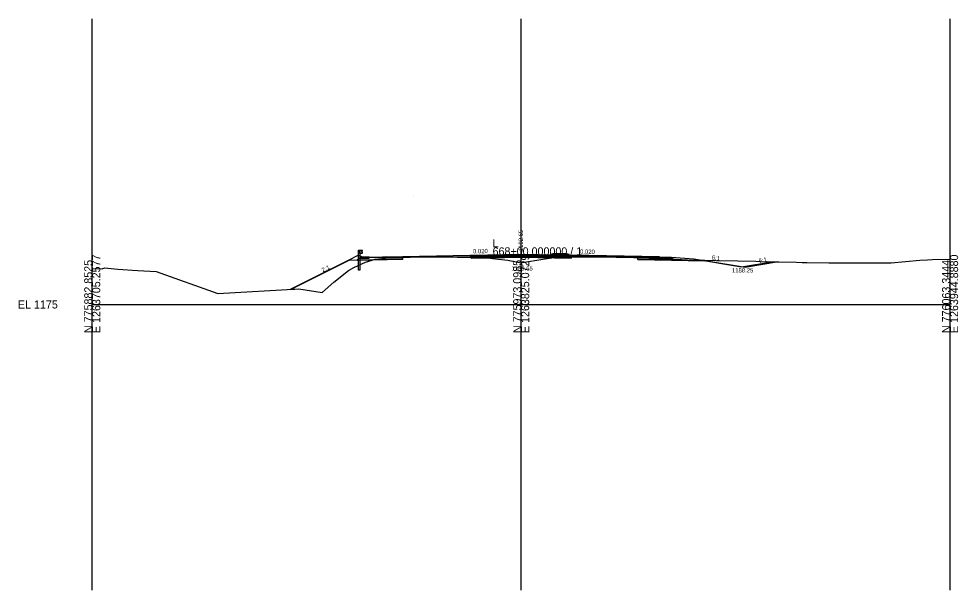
# Model space of a CAD drawing. Extents: x -41 to 1262860, y -100 to 777489.
# Drawn here: x -25.7 to 302.8, y 2435 to 2635 of the extents above; entities that cross this region are included whole.
import ezdxf

# ---------------------------------------------------------------- set-up
doc = ezdxf.new("R2010")
doc.units = 0
for name, color, linetype in [('Exist Cross Section Cell', 7, 'Continuous'), ('Exist XS Center Line Elevation Label', 7, 'Continuous'), ('Exist XS Ground Line', 7, 'Continuous'), ('Prop CMT Guardrail Graphics', 7, 'Continuous'), ('Prop CMT Pvmt Course 1', 7, 'Continuous'), ('Prop CMT Pvmt Course 4', 7, 'Continuous'), ('Prop CMT Pvmt Surface', 7, 'Continuous'), ('Prop CMT Shld Paved Course 1', 7, 'Continuous'), ('Prop CMT Shld Paved Course 2', 7, 'Continuous'), ('Prop CMT Shld Paved Course 4', 7, 'Continuous'), ('Prop CMT Slope Grass', 7, 'Continuous'), ('Prop CMT Subgrade Earthwork', 7, 'Continuous'), ('Prop Conc Curb and Gutter', 7, 'Continuous'), ('Prop Conc Island Cover', 7, 'Continuous'), ('Prop XS Ditch Standard Text', 7, 'Continuous'), ('Prop XS Earthwork Shape', 7, 'Continuous'), ('Prop XS Exc Vertical Line 1', 7, 'Continuous'), ('Prop XS Exc Vertical Line 2', 7, 'Continuous'), ('Prop XS Exc Vertical Line 3', 7, 'Continuous'), ('Prop XS Finish Grade', 7, 'Continuous'), ('Prop XS Hydro Elevations', 7, 'Continuous'), ('Prop XS SE Text', 7, 'Continuous'), ('Prop XS Side Slope Text', 7, 'Continuous'), ('Scratch_Level_4', 7, 'Continuous'), ('Scratch_Level_6', 7, 'Continuous'), ('Typical Curb CELL', 7, 'Continuous')]:
    doc.layers.add(name, color=color, linetype=linetype)

msp = doc.modelspace()

# ---------------------------------------------------------------- linework, layer by layer
at = {"layer": 'Exist Cross Section Cell'}
for p, q in [((150, 2535), (150, 2555)), ((0, 2535), (150, 2535)), ((150, 2535), (300, 2535))]:
    msp.add_line(p, q, dxfattribs=at)
at = {"layer": 'Exist XS Ground Line'}
msp.add_lwpolyline([(0, 2547.6), (3.47, 2547.54), (4.24, 2547.78), (8.95, 2547.37), (10.74, 2547.26), (14.03, 2547.01), (15.91, 2546.85), (22.35, 2546.58), (43.91, 2538.86), (72.29, 2540.43), (80.41, 2539.24), (84.48, 2542.76), (89.57, 2546.93), (91.48, 2547.93), (95.5, 2549.87), (98.14, 2550.65), (98.83, 2550.86), (102.58, 2551.18), (106.45, 2551.46), (108.07, 2551.54), (111.16, 2551.67), (120, 2551.72), (123.66, 2551.73), (134.58, 2551.43), (135.86, 2551.39), (135.97, 2551.39), (139.17, 2551.26), (139.43, 2551.23), (139.92, 2551.15), (145.28, 2550.51), (147.7, 2550.07), (150.05, 2549.64), (150.46, 2549.72), (157.54, 2550.92), (161.28, 2551.47), (162.98, 2551.54), (164.83, 2551.61), (170.78, 2551.65), (177.02, 2551.72), (189.41, 2551.47), (189.73, 2551.46), (189.77, 2551.46), (190.84, 2551.41), (196.52, 2551.13), (197.22, 2551.09), (200.74, 2550.94), (201.72, 2550.94), (208.2, 2550.67), (214.27, 2550.52), (218.16, 2550.35), (225.75, 2550.24), (232.05, 2550.15), (233.67, 2550.1), (238.66, 2549.93), (246.24, 2549.78), (248.32, 2549.74), (249.85, 2549.73), (257.58, 2549.6), (263.86, 2549.57), (269.63, 2549.57), (276.92, 2549.58), (278.52, 2549.57), (279.35, 2549.6), (289.37, 2550.47), (292.11, 2550.68), (293.83, 2550.76), (300, 2550.85)], dxfattribs=at)
at = {"layer": 'Prop CMT Guardrail Graphics'}
for p, q in [((93.11, 2554.05), (93.59, 2554.05)), ((93.11, 2551.55), (93.11, 2554.05)), ((93.59, 2552.87), (93.59, 2554.05)), ((93.59, 2554.05), (94.26, 2554.05)), ((93.59, 2554.05), (93.59, 2551.54)), ((94.26, 2552.87), (93.59, 2552.87)), ((94.26, 2554.05), (94.26, 2552.87)), ((94.26, 2553.97), (94.26, 2552.95)), ((94.36, 2553.95), (94.26, 2553.97)), ((94.26, 2552.95), (94.36, 2552.97)), ((94.27, 2553.5), (94.5, 2553.71)), ((94.27, 2553.41), (94.27, 2553.5)), ((94.5, 2553.21), (94.27, 2553.41)), ((94.5, 2553.85), (94.36, 2553.95)), ((94.36, 2552.97), (94.5, 2553.07)), ((94.5, 2553.71), (94.5, 2553.85)), ((94.5, 2553.07), (94.5, 2553.21)), ((93.11, 2547.05), (93.11, 2551.55)), ((93.59, 2551.54), (93.59, 2547.05)), ((93.59, 2547.05), (93.11, 2547.05))]:
    msp.add_line(p, q, dxfattribs=at)
at = {"layer": 'Prop CMT Pvmt Course 1'}
for p, q in [((132.5, 2552.05), (150, 2552.4)), ((150, 2552.4), (167.5, 2552.05))]:
    msp.add_line(p, q, dxfattribs=at)
for points in [[(108.5, 2551.57), (108.5, 2551.82), (108.5, 2551.82), (132.16, 2552.29), (132.16, 2552.29), (132.43, 2552.3), (132.43, 2552.3), (132.5, 2552.3), (132.5, 2552.05), (132.5, 2552.05), (132.43, 2552.05), (132.43, 2552.05), (132.16, 2552.04), (132.16, 2552.04), (108.5, 2551.57), (108.5, 2551.57), (108.5, 2551.57)], [(198.36, 2551.43), (198.36, 2551.68), (198.36, 2551.68), (167.5, 2552.3), (167.5, 2552.3), (167.5, 2552.05), (167.5, 2552.05), (167.5, 2552.05), (198.36, 2551.43), (198.36, 2551.43), (198.36, 2551.43)]]:
    msp.add_lwpolyline(points, dxfattribs=at)
at = {"layer": 'Prop CMT Pvmt Course 4'}
for p, q in [((108.5, 2550.78), (93.44, 2550.48)), ((132.5, 2551.72), (132.5, 2551.26)), ((132.5, 2551.26), (150, 2551.61)), ((150, 2551.61), (167.5, 2551.26)), ((190.84, 2550.79), (203.55, 2550.54)), ((198.36, 2550.64), (198.36, 2551.1)), ((203.08, 2551), (203.55, 2550.54))]:
    msp.add_line(p, q, dxfattribs=at)
at = {"layer": 'Prop CMT Pvmt Surface'}
for p, q in [((96.85, 2551.59), (108.5, 2551.82)), ((108.5, 2551.82), (132.5, 2552.3)), ((132.5, 2552.3), (150, 2552.65)), ((150, 2552.65), (167.5, 2552.3)), ((167.5, 2552.3), (198.36, 2551.68)), ((198.36, 2551.68), (202.48, 2551.6))]:
    msp.add_line(p, q, dxfattribs=at)
at = {"layer": 'Prop CMT Shld Paved Course 1'}
for p, q in [((94.5, 2551.54), (108.5, 2551.82)), ((108.5, 2551.57), (96.85, 2551.34)), ((104.5, 2551.74), (104.5, 2551.74)), ((108.5, 2551.82), (108.5, 2551.57)), ((108.5, 2551.57), (108.5, 2551.57)), ((132.5, 2552.3), (150, 2552.65)), ((150, 2552.65), (167.5, 2552.3))]:
    msp.add_line(p, q, dxfattribs=at)
msp.add_lwpolyline([(198.36, 2551.68), (202.48, 2551.6), (202.48, 2551.6), (202.74, 2551.34), (198.36, 2551.43), (198.36, 2551.43), (198.36, 2551.43), (198.36, 2551.68), (198.36, 2551.68)], dxfattribs=at)
at = {"layer": 'Prop CMT Shld Paved Course 2'}
for p, q in [((112.18, 2573.18), (112.18, 2573.18)), ((112.18, 2573.18), (112.18, 2573.18)), ((112.18, 2573.18), (112.18, 2573.18)), ((112.18, 2573.18), (112.18, 2573.18)), ((108.5, 2551.24), (101.64, 2551.1)), ((103.9, 2551.14), (103.9, 2551.14)), ((103.9, 2551.14), (103.9, 2551.14)), ((111.16, 2551.62), (108.5, 2551.57)), ((108.5, 2551.56), (109.05, 2551.58)), ((108.5, 2551.57), (108.5, 2551.24)), ((108.5, 2551.57), (108.5, 2551.57)), ((108.5, 2551.57), (108.5, 2551.56)), ((108.5, 2551.56), (108.5, 2551.56)), ((108.5, 2551.24), (108.5, 2551.24)), ((109.05, 2551.58), (111.16, 2551.62)), ((109.05, 2551.58), (109.05, 2551.58)), ((120, 2551.8), (111.16, 2551.62)), ((111.16, 2551.62), (114.6, 2551.69)), ((111.16, 2551.62), (111.16, 2551.62)), ((111.16, 2551.62), (111.16, 2551.62)), ((111.16, 2551.62), (111.16, 2551.62)), ((111.16, 2551.62), (111.16, 2551.62)), ((114.6, 2551.69), (120, 2551.72)), ((114.6, 2551.69), (114.6, 2551.69)), ((123.66, 2551.87), (120, 2551.8)), ((120, 2551.8), (120, 2551.8)), ((120, 2551.72), (123.66, 2551.73)), ((120, 2551.72), (120, 2551.72)), ((132.16, 2552.04), (123.66, 2551.87)), ((123.66, 2551.87), (123.66, 2551.87)), ((123.66, 2551.87), (123.66, 2551.87)), ((123.66, 2551.73), (123.66, 2551.73)), ((123.66, 2551.73), (127.63, 2551.62)), ((127.63, 2551.62), (132.16, 2551.71)), ((127.63, 2551.62), (127.63, 2551.62)), ((127.63, 2551.62), (127.63, 2551.62)), ((132.43, 2552.05), (132.16, 2552.04)), ((132.16, 2552.04), (132.16, 2552.04)), ((132.16, 2551.71), (132.16, 2551.71)), ((132.16, 2551.71), (132.43, 2551.71)), ((132.5, 2552.05), (132.43, 2552.05)), ((132.43, 2551.71), (132.5, 2551.72)), ((132.5, 2551.72), (150, 2552.07)), ((132.5, 2551.72), (132.5, 2552.05)), ((132.5, 2552.05), (132.5, 2552.05)), ((132.5, 2551.72), (132.5, 2551.72)), ((132.5, 2551.72), (132.5, 2551.72)), ((150, 2552.07), (167.5, 2551.72)), ((167.5, 2551.72), (167.5, 2552.05)), ((167.5, 2552.05), (170.78, 2551.98)), ((170.74, 2551.65), (167.5, 2551.72)), ((167.5, 2551.72), (167.5, 2551.72)), ((167.5, 2551.72), (167.5, 2551.72)), ((170.78, 2551.65), (170.74, 2551.65)), ((170.78, 2551.98), (170.78, 2551.98)), ((170.78, 2551.98), (177.02, 2551.86)), ((177.02, 2551.72), (170.78, 2551.65)), ((170.78, 2551.65), (170.78, 2551.65)), ((177.02, 2551.86), (177.02, 2551.86)), ((177.02, 2551.86), (177.02, 2551.86)), ((177.02, 2551.86), (189.41, 2551.61)), ((189.41, 2551.47), (177.02, 2551.72)), ((177.02, 2551.72), (177.02, 2551.72)), ((177.02, 2551.72), (177.02, 2551.72)), ((189.41, 2551.61), (189.41, 2551.61)), ((189.41, 2551.61), (189.73, 2551.61)), ((189.73, 2551.46), (189.41, 2551.47)), ((189.41, 2551.47), (189.41, 2551.47)), ((189.73, 2551.61), (189.77, 2551.6)), ((189.77, 2551.46), (189.73, 2551.46)), ((189.77, 2551.6), (189.77, 2551.6)), ((189.77, 2551.6), (190.84, 2551.58)), ((190.84, 2551.41), (189.77, 2551.46)), ((189.77, 2551.46), (189.77, 2551.46)), ((190.84, 2551.58), (190.84, 2551.58)), ((190.84, 2551.58), (190.84, 2551.58)), ((190.84, 2551.58), (190.84, 2551.58)), ((190.84, 2551.58), (190.84, 2551.58)), ((190.84, 2551.58), (196.52, 2551.47)), ((190.84, 2551.25), (190.84, 2551.41)), ((190.84, 2551.41), (190.84, 2551.41)), ((190.84, 2551.41), (190.84, 2551.41)), ((190.84, 2551.41), (190.84, 2551.41)), ((197.22, 2551.12), (190.84, 2551.25)), ((196.52, 2551.47), (197.22, 2551.46)), ((196.52, 2551.47), (196.52, 2551.47)), ((196.52, 2551.47), (196.52, 2551.47)), ((197.22, 2551.46), (197.22, 2551.46)), ((197.22, 2551.46), (198.36, 2551.43)), ((198.36, 2551.1), (197.22, 2551.12)), ((197.22, 2551.12), (197.22, 2551.12)), ((198.36, 2551.43), (198.36, 2551.1)), ((198.36, 2551.1), (198.36, 2551.1))]:
    msp.add_line(p, q, dxfattribs=at)
msp.add_lwpolyline([(198.36, 2551.43), (202.74, 2551.34), (202.74, 2551.34), (203.08, 2551), (198.36, 2551.1), (198.36, 2551.1), (198.36, 2551.1), (198.36, 2551.43), (198.36, 2551.43)], dxfattribs=at)
at = {"layer": 'Prop CMT Shld Paved Course 4'}
for p, q in [((112.18, 2573.18), (112.18, 2573.18)), ((112.18, 2573.18), (112.18, 2573.18)), ((92.58, 2550.46), (93.32, 2551.2)), ((93.32, 2551.2), (93.83, 2551.2)), ((103.9, 2551.14), (103.9, 2551.14)), ((108.5, 2551.24), (108.5, 2550.78)), ((127.63, 2551.62), (132.5, 2551.48)), ((167.5, 2551.72), (167.5, 2551.26)), ((170.74, 2551.65), (167.5, 2551.63)), ((190.84, 2550.79), (190.84, 2551.25)), ((198.36, 2551.1), (203.08, 2551)), ((198.36, 2551.1), (198.36, 2551.1)), ((203.08, 2551), (203.08, 2551))]:
    msp.add_line(p, q, dxfattribs=at)
at = {"layer": 'Prop CMT Slope Grass'}
for q in [(89.47, 2550.4), (93.83, 2551.88)]:
    msp.add_line((93.14, 2552.23), q, dxfattribs=at)
at = {"layer": 'Prop CMT Subgrade Earthwork'}
for p, q in [((108.5, 2550.78), (89.47, 2550.4)), ((108.5, 2550.78), (108.5, 2551.56)), ((150, 2551.61), (132.5, 2551.26)), ((132.5, 2551.26), (132.5, 2551.48)), ((167.5, 2551.26), (150, 2551.61)), ((167.5, 2551.63), (167.5, 2551.26)), ((190.84, 2550.79), (190.84, 2551.41)), ((190.84, 2550.79), (214.24, 2550.32))]:
    msp.add_line(p, q, dxfattribs=at)
at = {"layer": 'Prop Conc Curb and Gutter'}
for p, q in [((160.48, 2552.61), (161.23, 2552.86)), ((161.23, 2552.86), (162.23, 2552.88)), ((161.23, 2552.86), (161.23, 2552.86)), ((162.23, 2552.88), (162.23, 2552.44)), ((165.99, 2552.73), (164.99, 2552.75)), ((164.99, 2552.75), (164.99, 2552.31)), ((166.74, 2552.48), (165.99, 2552.73)), ((165.99, 2552.73), (165.99, 2552.73)), ((160.47, 2552.44), (160.48, 2552.61)), ((160.47, 2552.44), (160.47, 2552.44)), ((160.47, 2552.44), (160.47, 2552.32)), ((162.23, 2552.44), (160.47, 2552.44)), ((160.47, 2552.44), (160.47, 2552.44)), ((160.47, 2552.32), (160.47, 2552.32)), ((160.47, 2552.32), (162.23, 2552.32)), ((160.48, 2552.61), (160.48, 2552.61)), ((162.23, 2552.32), (162.23, 2552.44)), ((162.23, 2552.44), (162.23, 2552.44)), ((162.23, 2552.32), (162.23, 2552.32)), ((162.23, 2552.32), (162.23, 2552.32)), ((166.75, 2552.31), (164.99, 2552.31)), ((164.99, 2552.31), (164.99, 2552.19)), ((164.99, 2552.31), (164.99, 2552.31)), ((164.99, 2552.19), (164.99, 2552.19)), ((164.99, 2552.19), (166.75, 2552.19)), ((166.75, 2552.31), (166.74, 2552.48)), ((166.74, 2552.48), (166.74, 2552.48)), ((166.75, 2552.19), (166.75, 2552.31)), ((166.75, 2552.31), (166.75, 2552.31)), ((166.75, 2552.31), (166.75, 2552.31)), ((166.75, 2552.19), (166.75, 2552.19)), ((166.75, 2552.19), (166.75, 2552.19))]:
    msp.add_line(p, q, dxfattribs=at)
at = {"layer": 'Prop Conc Island Cover'}
for p, q in [((162.23, 2552.88), (162.23, 2552.63)), ((164.99, 2552.75), (162.23, 2552.88)), ((164.99, 2552.5), (164.99, 2552.75)), ((164.99, 2552.75), (164.99, 2552.75)), ((164.99, 2552.5), (162.23, 2552.63)), ((164.99, 2552.5), (164.99, 2552.5))]:
    msp.add_line(p, q, dxfattribs=at)
at = {"layer": 'Prop XS Earthwork Shape'}
for points in [[(97.84, 2550.56), (93.44, 2550.48), (89.7, 2550.4), (69.44, 2540.27), (72.29, 2540.43), (80.41, 2539.24), (84.48, 2542.76), (89.57, 2546.93), (91.48, 2547.93), (95.5, 2549.87)], [(98.83, 2550.86), (102.58, 2551.18), (106.45, 2551.46), (108.07, 2551.54), (108.5, 2551.56), (108.5, 2550.78), (97.84, 2550.56), (98.14, 2550.65)], [(132.5, 2551.26), (132.5, 2551.48), (134.58, 2551.43), (135.86, 2551.39), (135.97, 2551.39), (136.96, 2551.35)], [(139.17, 2551.26), (139.43, 2551.23), (139.92, 2551.15), (145.28, 2550.51), (147.7, 2550.07), (150.05, 2549.64), (150.46, 2549.72), (157.54, 2550.92), (160.78, 2551.39), (150, 2551.61), (136.96, 2551.35)], [(167.5, 2551.26), (160.78, 2551.39), (161.28, 2551.47), (162.98, 2551.54), (164.83, 2551.61), (167.5, 2551.63)], [(200.74, 2550.94), (201.72, 2550.94), (203.21, 2550.87), (203.55, 2550.54), (190.84, 2550.79), (190.84, 2551.41), (196.52, 2551.13), (197.22, 2551.09)], [(212.87, 2550.55), (214.24, 2550.32), (203.55, 2550.54), (203.21, 2550.87), (208.2, 2550.67)], [(233.67, 2550.1), (238.66, 2549.93), (239.97, 2549.91), (228.36, 2547.97), (214.24, 2550.32), (212.87, 2550.55), (214.27, 2550.52), (218.16, 2550.35), (225.75, 2550.24), (232.05, 2550.15)]]:
    msp.add_lwpolyline(points, close=True, dxfattribs=at)
at = {"layer": 'Prop XS Exc Vertical Line 1'}
msp.add_line((0, 2435), (0, 2635), dxfattribs=at)
at = {"layer": 'Prop XS Exc Vertical Line 2'}
msp.add_line((150, 2435), (150, 2635), dxfattribs=at)
at = {"layer": 'Prop XS Exc Vertical Line 3'}
msp.add_line((300, 2435), (300, 2635), dxfattribs=at)
at = {"layer": 'Prop XS Finish Grade'}
for p, q in [((89.47, 2550.4), (69.19, 2540.26)), ((202.48, 2551.6), (210.36, 2550.97)), ((202.48, 2551.6), (203.55, 2550.54)), ((210.36, 2550.97), (227, 2548.2)), ((227, 2548.2), (237.62, 2549.97))]:
    msp.add_line(p, q, dxfattribs=at)
at = {"layer": 'Scratch_Level_4'}
msp.add_line((300, 2435), (300, 2635), dxfattribs=at)
at = {"layer": 'Scratch_Level_6'}
msp.add_line((0, 2435), (0, 2635), dxfattribs=at)
at = {"layer": 'Typical Curb CELL'}
for p, q in [((93.83, 2551.2), (93.83, 2551.88)), ((94.52, 2551.53), (93.83, 2551.88)), ((93.83, 2551.2), (96.85, 2551.17)), ((93.87, 2551.5), (94.02, 2551.54)), ((94, 2551.45), (93.87, 2551.5)), ((94.02, 2551.54), (94, 2551.45)), ((94.54, 2551.41), (94.43, 2551.33)), ((94.43, 2551.33), (94.6, 2551.29)), ((96.84, 2551.59), (94.52, 2551.53)), ((94.6, 2551.29), (94.54, 2551.41)), ((95.28, 2551.46), (95.24, 2551.34)), ((95.24, 2551.34), (95.36, 2551.34)), ((95.36, 2551.34), (95.28, 2551.46)), ((95.78, 2551.4), (95.68, 2551.32)), ((95.68, 2551.32), (95.85, 2551.28)), ((95.85, 2551.28), (95.78, 2551.4)), ((96.53, 2551.44), (96.49, 2551.33)), ((96.49, 2551.33), (96.61, 2551.32)), ((96.61, 2551.32), (96.53, 2551.44)), ((96.85, 2551.59), (96.85, 2551.59)), ((96.85, 2551.17), (96.85, 2551.58))]:
    msp.add_line(p, q, dxfattribs=at)
for centre in [(93.9, 2551.58), (93.99, 2551.31), (94.11, 2551.36), (94.37, 2551.38), (94.38, 2551.33), (94.56, 2551.25), (94.59, 2551.35), (94.78, 2551.31), (94.83, 2551.42), (94.96, 2551.39), (94.99, 2551.27), (95.05, 2551.3), (95.24, 2551.3), (95.36, 2551.35), (95.45, 2551.34), (95.55, 2551.29), (95.61, 2551.43), (95.62, 2551.37), (95.63, 2551.32), (95.84, 2551.34), (96.03, 2551.29), (96.08, 2551.41), (96.13, 2551.38), (96.21, 2551.38), (96.24, 2551.25), (96.29, 2551.29), (96.36, 2551.46), (96.72, 2551.54), (96.76, 2551.41)]:
    msp.add_circle(centre, 0.00802, dxfattribs=at)
msp.add_arc((96.84, 2551.58), 0.0104, 359.4338, 91.4818, dxfattribs=at)

# ---------------------------------------------------------------- texts
at = {"layer": 'Exist Cross Section Cell'}
for s, p in [('L', (140, 2555)), ('668+00.000000 / 1', (140, 2552.2)), ('EL 1175', (-26, 2533.6))]:
    msp.add_text(s, height=2.8, dxfattribs=at).set_placement(p)
for s, p in [('N 775882.8525', (0, 2525)), ('E 1263705.2577', (2.8, 2525)), ('N 775973.0985', (150, 2525)), ('E 1263825.0729', (152.8, 2525)), ('N 776063.3444', (300, 2525)), ('E 1263944.8880', (302.8, 2525))]:
    msp.add_text(s, height=2.8, rotation=90, dxfattribs=at).set_placement(p)
at = {"layer": 'Exist XS Center Line Elevation Label'}
msp.add_text('1189.65', height=1.5, dxfattribs=at).set_placement((146.57, 2546.9))
at = {"layer": 'Prop XS Ditch Standard Text'}
msp.add_text('1188.25', height=1.5, dxfattribs=at).set_placement((223.7, 2546.21))
at = {"layer": 'Prop XS Hydro Elevations'}
msp.add_text('1192.65', height=1.5, rotation=90, dxfattribs=at).set_placement((150.6, 2553.66))
at = {"layer": 'Prop XS SE Text'}
for rotation, p in [(1.1458, (133.15, 2552.88)), (358.8542, (170.57, 2552.79))]:
    msp.add_text('0.020', height=1.5, rotation=rotation, dxfattribs=at).set_placement(p)
at = {"layer": 'Prop XS Side Slope Text'}
for s, rotation, p in [('6:1', 350.5377, (216.58, 2550.8)), ('6:1', 9.4809, (233.17, 2549.59)), ('2:1', 26.5651, (80.68, 2546.27))]:
    msp.add_text(s, height=1.5, rotation=rotation, dxfattribs=at).set_placement(p)

doc.saveas('drawing.dxf')
